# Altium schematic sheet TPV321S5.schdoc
size 127 x 101 mm
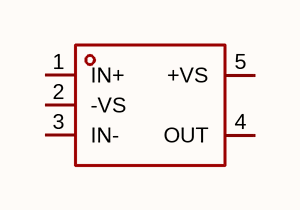
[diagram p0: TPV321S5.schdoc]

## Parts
U?  tpv321s5  [SOT-23-5_L2.9-W1.6-P0.95-LS2.8-BL]  (value not drawn)

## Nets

Not connected (* = marked no-connect by the designer): U? 1(IN+) 2(-VS) 3(IN-) 4(OUT) 5(+VS)

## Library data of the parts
U? = tpv321s5: 放大器数:1;轨到轨:轨到轨输入,轨到轨输出;增益带宽积(GBW):1MHz;输入失调电压(Vos):5mV;压摆率(SR):600V/ms;输入偏置电流(Ib):10pA;; Manufacturer: TECH PUBLIC(台舟); AddInBom: yes; ModelId: 018c57e721114987ae90467fe9f1d259; ModelTransform: 114.96,110.236,0,0,0,0,0,0,0; Number of Channels: 1; Maximum Power Supply Range (Vdd-Vss): 5.5V; Gain Bandwidth Product: 1MHz; Vos - Input Offset Voltage: 5mV; Input Offset Voltage Drift(Vos TC): 2uV/℃; Ib - Input Bias Current: 10pA; Input Voltage Noise Density: 20nV/√Hz@10kHz; Common Mode Rejection Ratio(CMRR): 80dB; Quiescent Current: 40uA; Output Current: 20mA; Single supply: 2.2V~5.5V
